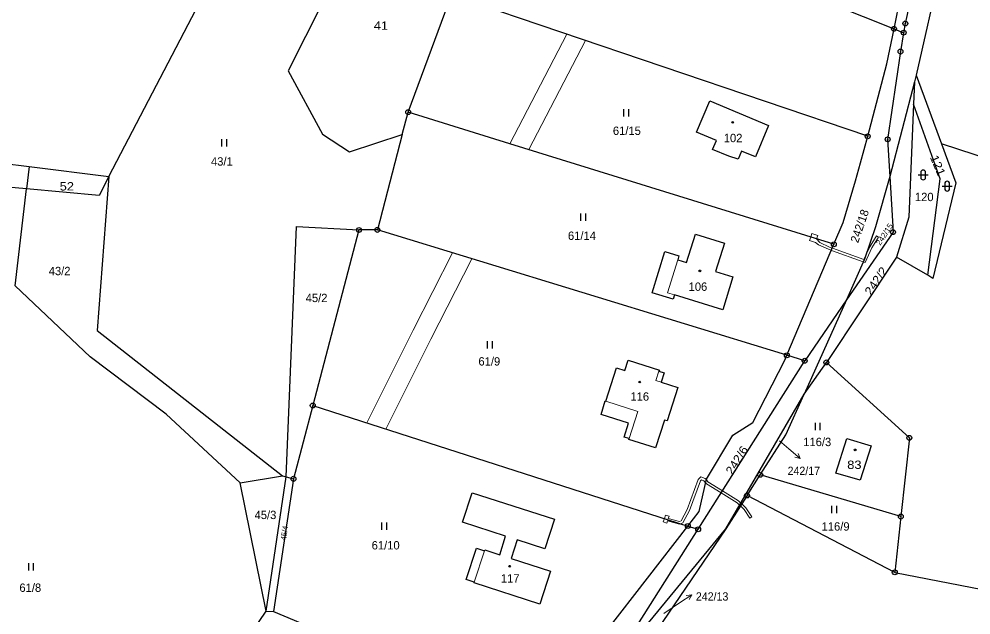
# Model space of a CAD drawing. Extents: x -632162 to -629607, y -1101195 to -1098670.
# Drawn here: x -632040.8 to -631847.3, y -1099286.3 to -1099165 of the extents above; entities that cross this region are included whole.
import ezdxf
from ezdxf.enums import TextEntityAlignment as Align

# ---------------------------------------------------------------- set-up
doc = ezdxf.new("R2010")
doc.units = 0
doc.header["$LTSCALE"] = 0.68
for name, color, linetype, lineweight in [('1', 7, 'Continuous', 25), ('13', 7, 'Continuous', 13), ('3', 7, 'Continuous', 25), ('4', 7, 'Continuous', 13), ('5', 7, 'Continuous', 25), ('7', 7, 'Continuous', 13), ('8', 7, 'Continuous', 25)]:
    doc.layers.add(name, color=color, linetype=linetype, lineweight=lineweight)
doc.layers.add('2', color=7, linetype='Continuous')

msp = doc.modelspace()

# ---------------------------------------------------------------- linework, layer by layer
at = {"layer": '1'}
for p, q in [((-631868.28, -1099188.89), (-631952.92, -1099160.15)), ((-631862.93, -1099167.03), (-631860.97, -1099167.82)), ((-631860.63, -1099165.93), (-631860.97, -1099167.82)), ((-631858.39, -1099176.43), (-631853.29, -1099190.4)), ((-631858.76, -1099177.83), (-631863.78, -1099197.1)), ((-631962.91, -1099188.51), (-631967.99, -1099207.93)), ((-632038.8, -1099195.05), (-632039.33, -1099199.61)), ((-631884.72, -1099233.45), (-631875.17, -1099210.86)), ((-631872.56, -1099222.14), (-631881.09, -1099234.56)), ((-631897.11, -1099268.73), (-631881.23, -1099241.37)), ((-631995.89, -1099259.41), (-631987.25, -1099257.99)), ((-631990.57, -1099285.5), (-631986.51, -1099258.18)), ((-631986.51, -1099258.18), (-631985.04, -1099258.56)), ((-631892.81, -1099261.96), (-631890.13, -1099257.75)), ((-631861.54, -1099266.25), (-631890.13, -1099257.75)), ((-631862.77, -1099277.6), (-631761.39, -1099297.42)), ((-631990.57, -1099285.5), (-631989.09, -1099285.54))]:
    msp.add_line(p, q, dxfattribs=at)
for points in [[(-631849.77, -1099064.73), (-631849.52, -1099070.31), (-631850.41, -1099080.83), (-631852.1, -1099103.84), (-631855.83, -1099144.06), (-631860.63, -1099165.93)], [(-632123.73, -1099184.2), (-632102.04, -1099186.98), (-632044.3, -1099194.37), (-632038.8, -1099195.05), (-632022.59, -1099197.06), (-631982.3, -1099119.85)], [(-631982.3, -1099119.85), (-631956.97, -1099131.45), (-631959.75, -1099137.93), (-631972, -1099147.54), (-631986.15, -1099175.57), (-631979.13, -1099188.49), (-631973.64, -1099192.07), (-631962.91, -1099188.51), (-631961.73, -1099183.99), (-631952.92, -1099160.15), (-631943.5, -1099134.63)], [(-631851.51, -1099153.18), (-631852.09, -1099153.47), (-631853.47, -1099154.53), (-631858.39, -1099176.43)], [(-631868.28, -1099188.89), (-631864.36, -1099174.16), (-631862.93, -1099167.03)], [(-631860.97, -1099167.82), (-631861.61, -1099171.66), (-631864.22, -1099189.52), (-631863.78, -1099197.1)], [(-631858.39, -1099176.43), (-631858.76, -1099177.83), (-631858.95, -1099182.39)], [(-631858.95, -1099182.39), (-631859.91, -1099205.36), (-631862.4, -1099213.45)], [(-631856.08, -1099217.16), (-631853.53, -1099197.55), (-631858.95, -1099182.39)], [(-631875.17, -1099210.86), (-631941.05, -1099190.41), (-631961.73, -1099183.99)], [(-631875.17, -1099210.86), (-631873.3, -1099206.44), (-631870.78, -1099197.96), (-631869.71, -1099194.27), (-631868.28, -1099188.89)], [(-631853.29, -1099190.4), (-631850.37, -1099198.36), (-631855.01, -1099217.79), (-631856.08, -1099217.16)], [(-631761.39, -1099297.42), (-631753.62, -1099269.88), (-631744.34, -1099249.71), (-631731.64, -1099230.17), (-631853.29, -1099190.4)], [(-632022.59, -1099197.06), (-632024.53, -1099200.96), (-632039.33, -1099199.61)], [(-632022.59, -1099197.06), (-632024.95, -1099228.41), (-631987.25, -1099257.99), (-631986.51, -1099258.18)], [(-631863.78, -1099197.1), (-631866.68, -1099207.29), (-631868.95, -1099213.89), (-631872.56, -1099222.14)], [(-631863.78, -1099197.1), (-631863.13, -1099208.39), (-631872.56, -1099222.14)], [(-631995.89, -1099259.41), (-632010.96, -1099245.45), (-632026.36, -1099233.77), (-632041.61, -1099219.33), (-632039.33, -1099199.61), (-632047.15, -1099198.89), (-632095.57, -1099275.62)], [(-631986.51, -1099258.18), (-631984.42, -1099207.27), (-631971.72, -1099207.95)], [(-631884.72, -1099233.45), (-631967.99, -1099207.93), (-631971.72, -1099207.95), (-631981.12, -1099243.66), (-631904.85, -1099268.17)], [(-631856.08, -1099217.16), (-631862.4, -1099213.45), (-631876.69, -1099234.89)], [(-631872.56, -1099222.14), (-631881.23, -1099241.37), (-631876.69, -1099234.89)], [(-631934.59, -1099313.53), (-631930.33, -1099304.63), (-631921.29, -1099289.36), (-631904.85, -1099268.17), (-631902.76, -1099268.84), (-631881.09, -1099234.56), (-631884.72, -1099233.45)], [(-631904.85, -1099268.17), (-631902.58, -1099265.24), (-631901.06, -1099258.67), (-631895.68, -1099249.66), (-631891.64, -1099247.14), (-631885.11, -1099234.4), (-631884.72, -1099233.45)], [(-631876.69, -1099234.89), (-631859.81, -1099250.25), (-631861.54, -1099266.25)], [(-631890.13, -1099257.75), (-631884.94, -1099249.59), (-631881.23, -1099241.37)], [(-631981.12, -1099243.66), (-631985.04, -1099258.56), (-631989.09, -1099285.54)], [(-632019.67, -1099329.26), (-632018.8, -1099327.1), (-631990.57, -1099285.5), (-631995.89, -1099259.41)], [(-631892.81, -1099261.96), (-631897.11, -1099268.73), (-631911.06, -1099289.31)], [(-631861.54, -1099266.25), (-631862.77, -1099277.6), (-631892.81, -1099261.96)], [(-631934.59, -1099313.53), (-631932.78, -1099316.31), (-631902.76, -1099268.84)], [(-631921.47, -1099300.99), (-631920.47, -1099299.28), (-631915.97, -1099291.61), (-631912.88, -1099287.86), (-631897.11, -1099268.73)], [(-631989.09, -1099285.54), (-631966.35, -1099295.14), (-631937.79, -1099308.63), (-631934.59, -1099313.53)]]:
    msp.add_lwpolyline(points, dxfattribs=at)
for points in [[(-631881.49, -1099159.57), (-631862.93, -1099167.03), (-631861.61, -1099160.43), (-631864.38, -1099159.32), (-631880.18, -1099152.99)], [(-631903.06, -1099188.06), (-631900.37, -1099181.7), (-631888.44, -1099186.72), (-631891.11, -1099193.08), (-631893.91, -1099191.9), (-631894.61, -1099193.56), (-631896.55, -1099192.95), (-631899.84, -1099191.57), (-631899.03, -1099189.75)], [(-631903.3, -1099208.81), (-631897.43, -1099210.62), (-631899.21, -1099216.4), (-631895.7, -1099217.48), (-631897.77, -1099224.2), (-631907.56, -1099221.16), (-631907.84, -1099222.01), (-631912.08, -1099220.71), (-631909.52, -1099212.35), (-631906.67, -1099213.18), (-631906.92, -1099214.02), (-631905.11, -1099214.59)], [(-631917, -1099234.41), (-631910.64, -1099236.44), (-631910.72, -1099236.68), (-631909.7, -1099237.01), (-631910.29, -1099238.91), (-631906.86, -1099240.01), (-631909.07, -1099246.79), (-631909.59, -1099246.65), (-631911.41, -1099252.29), (-631916.85, -1099250.56), (-631916.8, -1099250.39), (-631917.8, -1099250.07), (-631916.91, -1099247.26), (-631922.51, -1099245.46), (-631921.63, -1099242.73), (-631921.54, -1099242.76), (-631919.34, -1099236.02), (-631917.68, -1099236.55)], [(-631867.55, -1099251.85), (-631869.78, -1099258.82), (-631874.76, -1099257.44), (-631872.5, -1099250.38)], [(-631931.99, -1099266.8), (-631933.96, -1099272.8), (-631939.54, -1099271.01), (-631940.75, -1099274.78), (-631932.8, -1099277.36), (-631934.95, -1099284.04), (-631948.32, -1099279.72), (-631948.27, -1099279.58), (-631949.9, -1099279.04), (-631947.83, -1099272.69), (-631946.22, -1099273.22), (-631946.16, -1099273.04), (-631943.08, -1099274.03), (-631941.91, -1099270.24), (-631950.69, -1099267.42), (-631948.73, -1099261.4)]]:
    msp.add_lwpolyline(points, close=True, dxfattribs=at)
at = {"layer": '13'}
for points in [[(-631925.65, -1099169.41), (-631929.48, -1099168.11), (-631941.05, -1099190.41), (-631937.17, -1099191.61)], [(-631876.05, -1099211.42), (-631877.98, -1099210.53), (-631878.67, -1099209.77), (-631879.85, -1099209.41), (-631880.08, -1099210.11), (-631878.89, -1099210.48), (-631878.28, -1099210.95), (-631876.23, -1099211.88), (-631875.69, -1099212.08), (-631875.49, -1099211.62)], [(-631878.44, -1099209.05), (-631879.63, -1099208.68), (-631879.85, -1099209.41), (-631878.67, -1099209.77)], [(-631875.63, -1099212.1), (-631869.18, -1099214.42), (-631868.81, -1099214.55), (-631867.43, -1099211.61), (-631866.07, -1099209.43), (-631866.5, -1099209.16), (-631867.87, -1099211.37), (-631868.67, -1099213.08), (-631869.07, -1099213.93), (-631875.46, -1099211.63), (-631875.49, -1099211.62), (-631875.69, -1099212.08)], [(-631957.12, -1099230.15), (-631948.8, -1099213.81), (-631952.68, -1099212.62), (-631960.69, -1099228.34), (-631970.11, -1099247.2), (-631966.26, -1099248.44)], [(-631897.81, -1099261.02), (-631900.76, -1099259.18), (-631901.09, -1099258.79), (-631901.31, -1099258.53), (-631902.21, -1099258.15), (-631902.73, -1099258.74), (-631904.98, -1099264.83), (-631906.23, -1099267.13), (-631906.55, -1099267.27), (-631908.82, -1099266.63), (-631908.67, -1099266.16), (-631909.38, -1099265.93), (-631909.61, -1099266.64), (-631906.31, -1099267.7), (-631905.87, -1099267.53), (-631904.52, -1099265.03), (-631902.29, -1099259), (-631902.07, -1099258.75), (-631901.61, -1099258.95), (-631901.23, -1099259.39), (-631901.08, -1099259.56), (-631898.08, -1099261.43)], [(-631897.81, -1099261.02), (-631898.08, -1099261.43), (-631894.82, -1099263.47), (-631894.33, -1099263.93), (-631894.16, -1099264.09), (-631893.89, -1099263.66), (-631894.07, -1099263.49), (-631894.52, -1099263.07)], [(-631893.89, -1099263.66), (-631894.16, -1099264.09), (-631893.42, -1099264.78), (-631892.23, -1099266.56), (-631891.81, -1099266.28), (-631893.04, -1099264.46)], [(-631909.61, -1099266.64), (-631909.84, -1099267.35), (-631909.13, -1099267.58), (-631908.97, -1099267.11), (-631906.53, -1099267.79), (-631906.31, -1099267.7)]]:
    msp.add_lwpolyline(points, close=True, dxfattribs=at)
at = {"layer": '3'}
for p, q in [((-631917.881, -1099184.9), (-631917.881, -1099183.4)), ((-631916.88, -1099184.9), (-631916.88, -1099183.4)), ((-631999.611, -1099190.95), (-631999.611, -1099189.45)), ((-631998.61, -1099190.95), (-631998.61, -1099189.45)), ((-631857.501, -1099196.251), (-631857.501, -1099197.252)), ((-631856.499, -1099197.252), (-631856.499, -1099196.251)), ((-631858.001, -1099196.751), (-631855.999, -1099196.751)), ((-631853.121, -1099199.041), (-631851.119, -1099199.041)), ((-631852.621, -1099198.541), (-631852.621, -1099199.542)), ((-631851.619, -1099199.542), (-631851.619, -1099198.541)), ((-631926.591, -1099206.09), (-631926.591, -1099204.59)), ((-631925.59, -1099206.09), (-631925.59, -1099204.59)), ((-631945.601, -1099232.05), (-631945.601, -1099230.55)), ((-631944.6, -1099232.05), (-631944.6, -1099230.55)), ((-631878.921, -1099248.65), (-631878.921, -1099247.15)), ((-631877.92, -1099248.65), (-631877.92, -1099247.15)), ((-631875.551, -1099265.58), (-631875.551, -1099264.08)), ((-631874.55, -1099265.58), (-631874.55, -1099264.08)), ((-631967.091, -1099268.98), (-631967.091, -1099267.48)), ((-631966.09, -1099268.98), (-631966.09, -1099267.48)), ((-632038.891, -1099277.23), (-632038.891, -1099275.73)), ((-632037.89, -1099277.23), (-632037.89, -1099275.73))]:
    msp.add_line(p, q, dxfattribs=at)
for centre, start, end in [((-631857, -1099196.2509), 0, 180), ((-631857, -1099197.2509), 180, 359.98789), ((-631852.12, -1099198.5409), 0, 180), ((-631852.12, -1099199.5409), 180, 359.98789)]:
    msp.add_arc(centre, 0.5, start, end, dxfattribs=at)
at = {"layer": '4'}
for p, q in [((-631908.99, -1099220.71), (-631906.92, -1099214.02)), ((-631907.56, -1099221.16), (-631908.99, -1099220.71)), ((-631911.33, -1099238.57), (-631910.72, -1099236.68)), ((-631910.29, -1099238.91), (-631911.33, -1099238.57)), ((-631921.54, -1099242.76), (-631915.04, -1099244.87)), ((-631915.04, -1099244.87), (-631916.8, -1099250.39)), ((-631948.27, -1099279.58), (-631946.22, -1099273.22))]:
    msp.add_line(p, q, dxfattribs=at)
at = {"layer": '5'}
for centre in [(-631895.7368, -1099186.0592), (-631902.4068, -1099216.2692), (-631914.6368, -1099238.8792), (-631870.8368, -1099252.6892), (-631941.0768, -1099276.3492)]:
    msp.add_circle(centre, 0.175, dxfattribs=at)
at = {"layer": '7'}
for p, q in [((-631882.001, -1099254.419), (-631882.446, -1099253.392)), ((-631904.052, -1099282.152), (-631905.162, -1099282.297))]:
    msp.add_line(p, q, dxfattribs=at)
for points in [[(-631886.24, -1099250.87), (-631884.3, -1099252.49), (-631882.001, -1099254.419), (-631883.09, -1099254.159)], [(-631909.74, -1099285.98), (-631906.54, -1099283.83), (-631904.052, -1099282.152), (-631904.602, -1099283.127)]]:
    msp.add_lwpolyline(points, dxfattribs=at)
at = {"layer": '8'}
for centre, radius in [((-631860.63, -1099165.9299), 0.5), ((-631862.93, -1099167.0299), 0.5), ((-631862.93, -1099167.0299), 0.0303), ((-631860.97, -1099167.8199), 0.5), ((-631860.63, -1099165.9299), 0.0303), ((-631860.97, -1099167.8199), 0.0303), ((-631861.61, -1099171.6599), 0.5), ((-631861.61, -1099171.6599), 0.0303), ((-631961.73, -1099183.9899), 0.5), ((-631961.73, -1099183.9899), 0.0303), ((-631868.28, -1099188.8899), 0.5), ((-631868.28, -1099188.8899), 0.0303), ((-631864.22, -1099189.5199), 0.5), ((-631864.22, -1099189.5199), 0.0303), ((-631971.72, -1099207.9499), 0.5), ((-631971.72, -1099207.9499), 0.0303), ((-631967.99, -1099207.9299), 0.5), ((-631967.99, -1099207.9299), 0.0303), ((-631863.13, -1099208.3899), 0.5), ((-631863.13, -1099208.3899), 0.0303), ((-631875.17, -1099210.8599), 0.5), ((-631875.17, -1099210.8599), 0.0303), ((-631884.72, -1099233.4499), 0.5), ((-631884.72, -1099233.4499), 0.0303), ((-631881.09, -1099234.5599), 0.5), ((-631881.09, -1099234.5599), 0.0303), ((-631876.69, -1099234.8899), 0.5), ((-631876.69, -1099234.8899), 0.0303), ((-631981.12, -1099243.6599), 0.5), ((-631981.12, -1099243.6599), 0.0303), ((-631859.81, -1099250.2499), 0.5), ((-631859.81, -1099250.2499), 0.0303), ((-631985.04, -1099258.5599), 0.5), ((-631890.13, -1099257.7499), 0.5), ((-631890.13, -1099257.7499), 0.0303), ((-631985.04, -1099258.5599), 0.0303), ((-631892.81, -1099261.9599), 0.5), ((-631892.81, -1099261.9599), 0.0303), ((-631861.54, -1099266.2499), 0.5), ((-631861.54, -1099266.2499), 0.0303), ((-631904.85, -1099268.1699), 0.5), ((-631904.85, -1099268.1699), 0.0303), ((-631902.76, -1099268.8399), 0.5), ((-631902.76, -1099268.8399), 0.0303), ((-631862.77, -1099277.5999), 0.5), ((-631862.77, -1099277.5999), 0.0303)]:
    msp.add_circle(centre, radius, dxfattribs=at)

# ---------------------------------------------------------------- texts
at = {"layer": '2', "width": 1.15}
for s, p in [('41', (-631967.26, -1099167.23)), ('52', (-632031.13, -1099199.92)), ('83', (-631870.99, -1099256.56))]:
    msp.add_text(s, height=1.7, dxfattribs=at).set_placement(p, align=Align.CENTER)
at = {"layer": '2'}
for s, p in [('61/15', (-631917.25, -1099188.62)), ('102', (-631895.649, -1099190.09)), ('43/1', (-631999.61, -1099194.86)), ('120', (-631856.779, -1099202.08)), ('61/14', (-631926.39, -1099209.97)), ('43/2', (-632032.6, -1099217.15)), ('106', (-631902.799, -1099220.33)), ('45/2', (-631980.35, -1099222.62)), ('61/9', (-631945.22, -1099235.53)), ('116', (-631914.629, -1099242.676)), ('116/3', (-631878.54, -1099251.92)), ('45/3', (-631990.74, -1099266.76)), ('116/9', (-631874.81, -1099269.11)), ('61/10', (-631966.3, -1099272.94)), ('61/8', (-632038.56, -1099281.57)), ('117', (-631940.979, -1099279.676))]:
    msp.add_text(s, height=1.7, dxfattribs=at).set_placement(p, align=Align.CENTER)
for s, height, rotation, width, p in [('121', 1.7, 293, 1.15, (-631854.7983, -1099195.1534)), ('242/15', 1.14, 57, 1.05, (-631864.397, -1099209.1424)), ('242/2', 1.7, 56, 1.1, (-631865.8714, -1099218.7878)), ('242/6', 1.7, 58, 1.1, (-631894.1708, -1099255.2299))]:
    msp.add_text(s, height=height, rotation=rotation, dxfattribs=dict(at, width=width)).set_placement(p, align=Align.CENTER)
for s, height, rotation, p in [('242/18', 1.7, 71, (-631869.1124, -1099207.4222)), ('45/4', 1.14, 82, (-631986.3174, -1099269.6858))]:
    msp.add_text(s, height=height, rotation=rotation, dxfattribs=at).set_placement(p, align=Align.CENTER)
at = {"layer": '2', "width": 0.95}
for s, p in [('242/17', (-631884.57, -1099257.803)), ('242/13', (-631903.22, -1099283.353))]:
    msp.add_text(s, height=1.7, dxfattribs=at).set_placement(p)

doc.saveas('drawing.dxf')
